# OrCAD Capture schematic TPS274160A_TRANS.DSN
size C; title: TPS274160A: 40-V, 160-mOhm Quad-Channel Industrial Smart; rev: 1.0; note: Datasheet: SLVSF05     EVM: NA; note: High-Side Switch
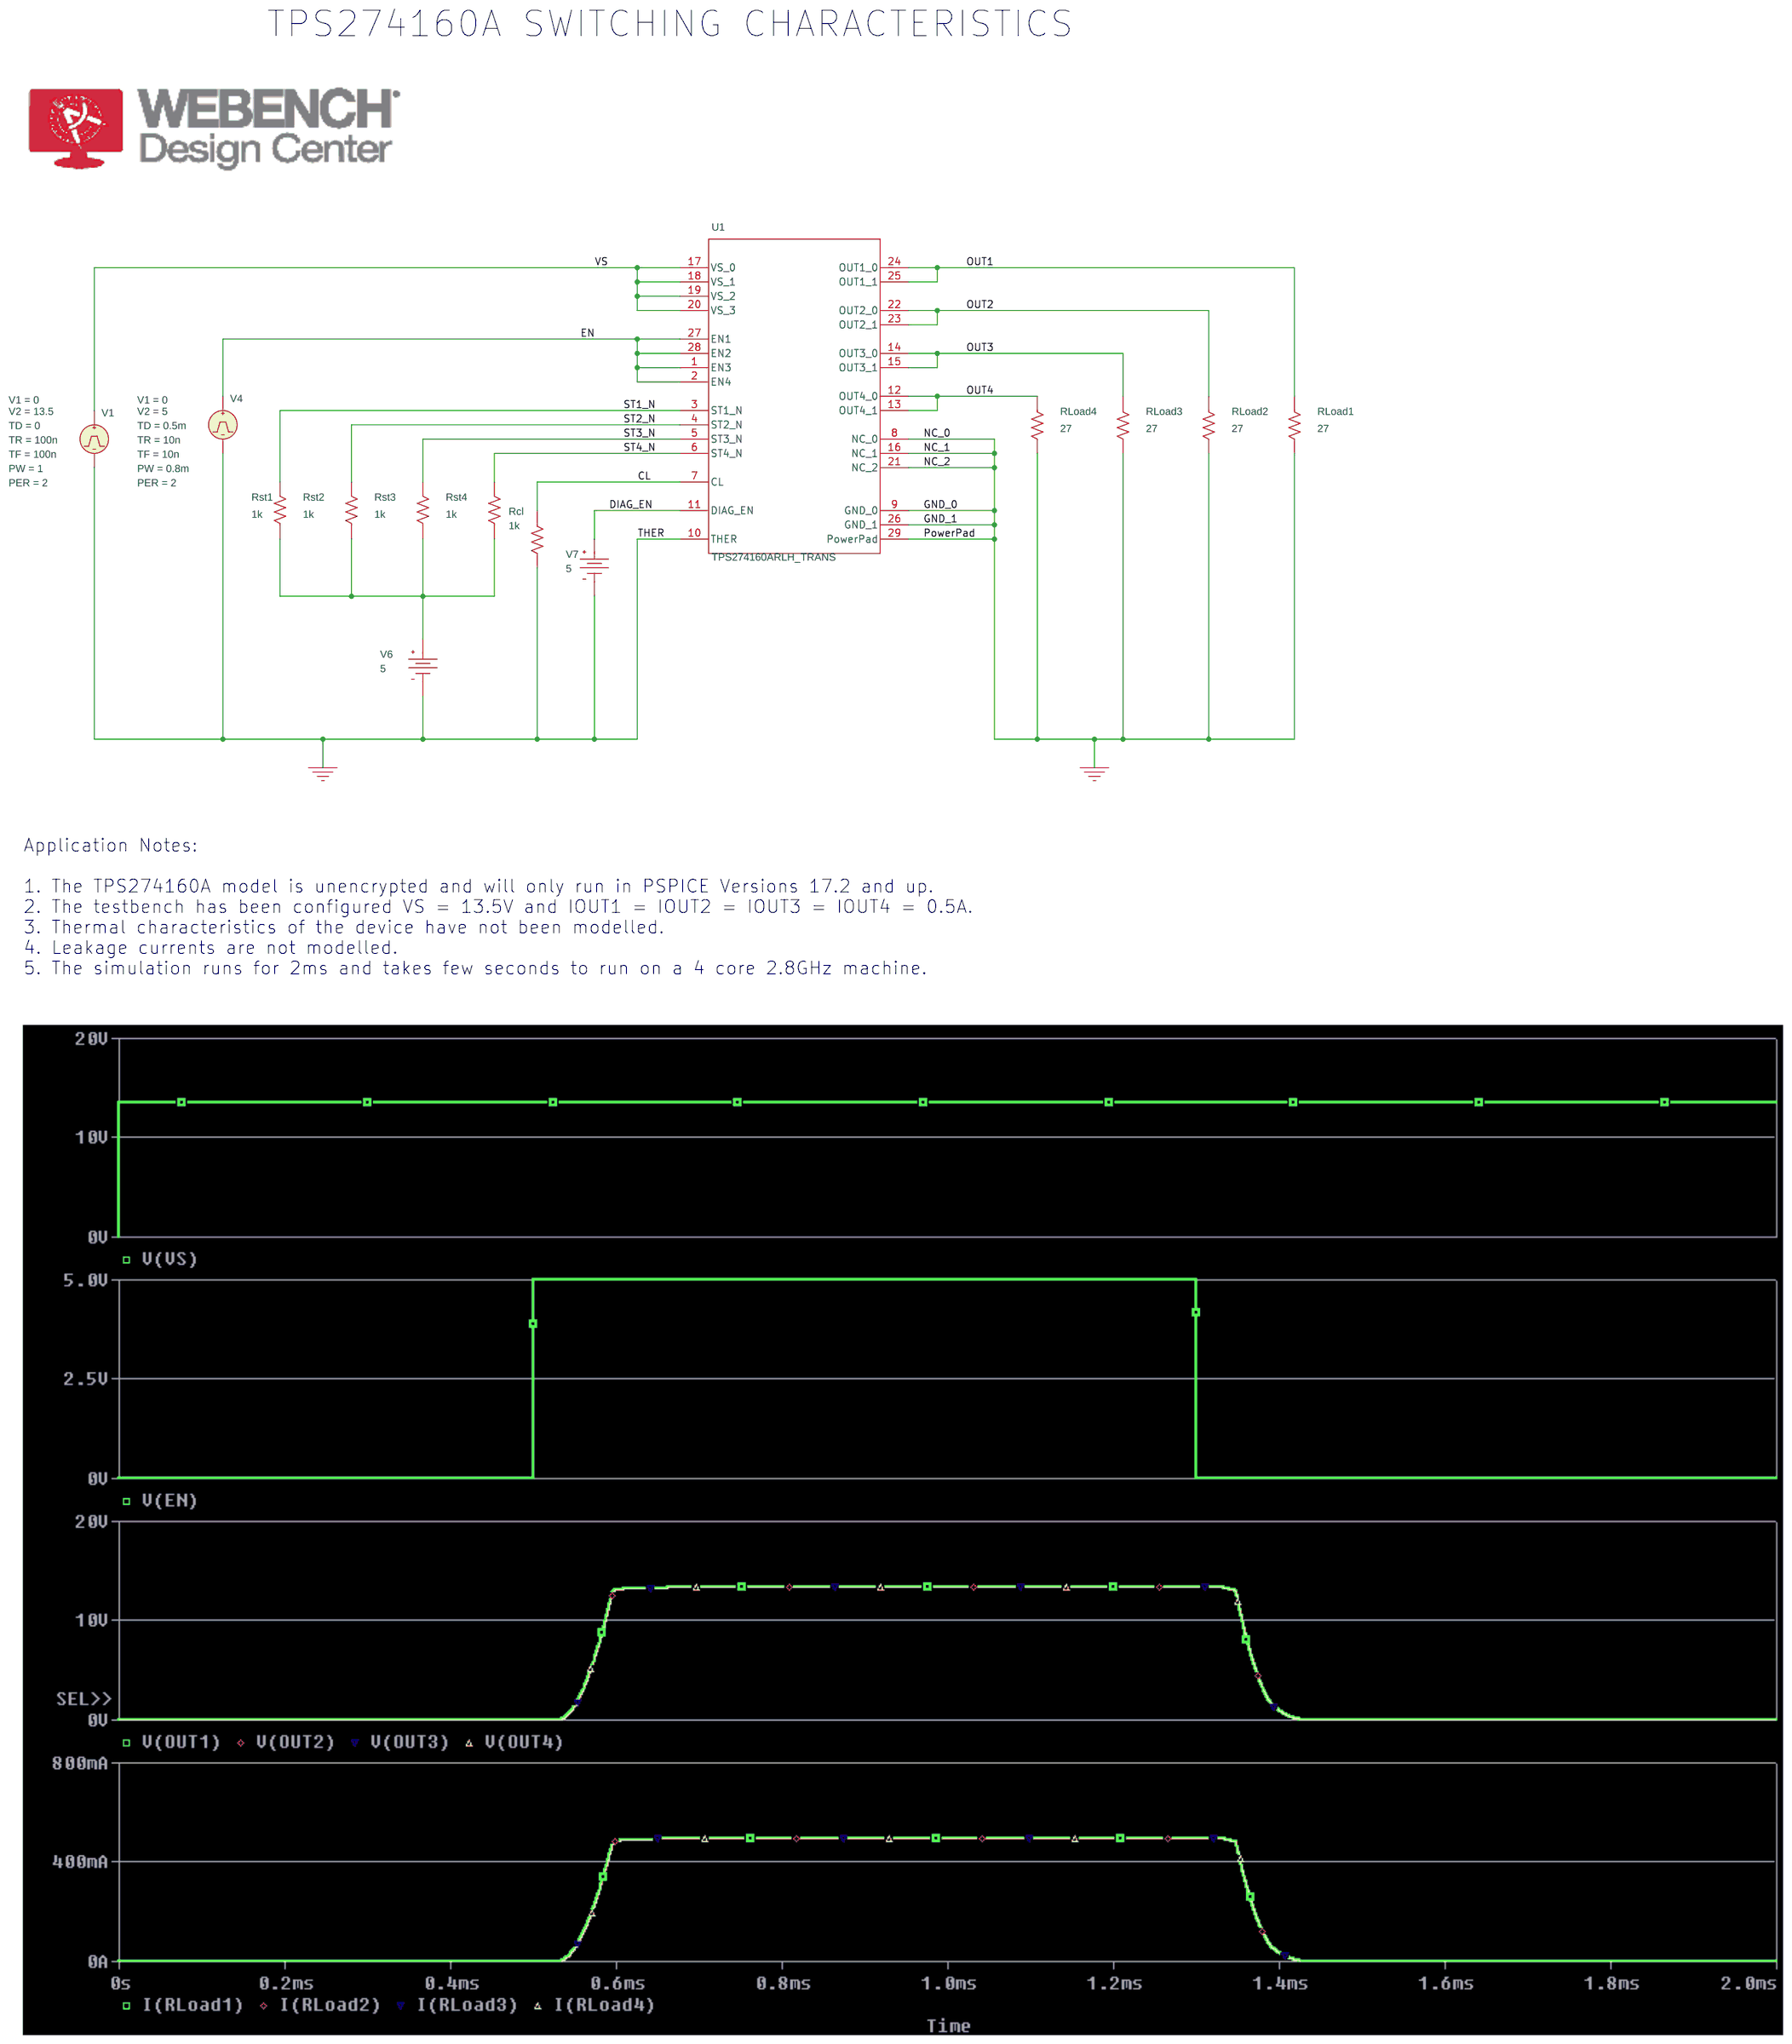
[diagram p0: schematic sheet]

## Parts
Rcl  1k  [AX/RC05]
RLoad1  27  [AX/RC05]
RLoad2  27  [AX/RC05]
RLoad3  27  [AX/RC05]
RLoad4  27  [AX/RC05]
Rst1  1k  [AX/RC05]
Rst2  1k  [AX/RC05]
Rst3  1k  [AX/RC05]
Rst4  1k  [AX/RC05]
U1  TPS274160ARLH_TRANS  [RLH0028A-IPC_A]
V1  VPULSE
V4  VPULSE
V6  VDC
V7  VDC

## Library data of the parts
Rcl RLoad1-RLoad4 Rst1-Rst4 = R
U1 = TPS274160ARLH_TRANS
V1 = VPULSE: PER: 2; PW: 1; TD: 0; TF: 100n; TR: 100n; V1: 0; V2: 13.5
V4 = VPULSE: PER: 2; PW: 0.8m; TD: 0.5m; TF: 10n; TR: 10n; V1: 0; V2: 5
V6 V7 = VDC: DC: 5

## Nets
0: Rcl.2 RLoad1.2 RLoad2.2 RLoad3.2 RLoad4.2 U1.8(NC_0) U1.9(GND_0) U1.10(THER) U1.16(NC_1) U1.21(NC_2) U1.26(GND_1) U1.29(PowerPad) V1.2(-) V4.2(-) V6.1(-) V7.1(-)
CL: Rcl.1 U1.7(CL)
DIAG_EN: U1.11(DIAG_EN) V7.0(+)
EN: U1.1(EN3) U1.2(EN4) U1.27(EN1) U1.28(EN2) V4.1(+)
OUT1: RLoad1.1 U1.24(OUT1_0) U1.25(OUT1_1)
OUT2: RLoad2.1 U1.22(OUT2_0) U1.23(OUT2_1)
OUT3: RLoad3.1 U1.14(OUT3_0) U1.15(OUT3_1)
OUT4: RLoad4.1 U1.12(OUT4_0) U1.13(OUT4_1)
ST1_N: Rst1.2 U1.3(ST1_N)
ST2_N: Rst2.2 U1.4(ST2_N)
ST3_N: Rst3.2 U1.5(ST3_N)
ST4_N: Rst4.2 U1.6(ST4_N)
VS: U1.17(VS_0) U1.18(VS_1) U1.19(VS_2) U1.20(VS_3) V1.1(+)
N16825491: Rst1.1 Rst2.1 Rst3.1 Rst4.1 V6.0(+)

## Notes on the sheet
- TPS274160A SWITCHING CHARACTERISTICS
- Application Notes:
  1. The TPS274160A model is unencrypted and will only run in PSPICE Versions 17.2 and up.
  2. The testbench has been configured VS = 13.5V and IOUT1 = IOUT2 = IOUT3 = IOUT4 = 0.5A.
  3. Thermal characteristics of the device have not been modelled.
  4. Leakage currents are not modelled.
  5. The simulation runs for 2ms and takes few seconds to run on a 4 core 2.8GHz machine.
